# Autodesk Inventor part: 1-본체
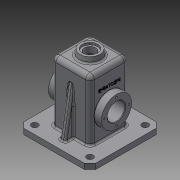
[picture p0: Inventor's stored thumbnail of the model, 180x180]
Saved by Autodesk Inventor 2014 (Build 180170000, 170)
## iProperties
Created: 2016-02
Part Number: 1-본체
Material: 일반
Document SubType Name: Modeling
Designer: HGY
Density: 1 g/cm^3
Appearance: 기본값
Author: HGY
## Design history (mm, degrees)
sketch "스케치1"
  geometry: L1 (-35, 35)-(35, 35); L2 (35, 35)-(35, -35); L3 (35, -35)-(-35, -35); L4 (-35, -35)-(-35, 35); L5 (-35, 35)-(35, -35); L6 (35, 35)-(-35, -35); 1 further point
  constraints: 12 end point, 2 midpoint, 2 parallel, 2 perpendicular, 1 horizontal
  dimensions: "d0" = 70 distance of L1.end L2.end
extrude "돌출1" new body sketch "스케치1" distance "d1" = 120; taper "d2" = 0 deg
sketch "스케치2"
  geometry: L1 (-65, 65)-(65, 65); L2 (65, 65)-(65, -65); L3 (65, -65)-(-65, -65); L4 (-65, -65)-(-65, 65); L5 (-65, 65)-(65, -65); L6 (65, 65)-(-65, -65); 1 further point
  constraints: 12 end point, 2 midpoint, 2 parallel, 2 perpendicular, 1 horizontal
  dimensions: "d3" = 130 distance of L1.end L2.end
extrude "돌출2" join sketch "스케치2" distance "d4" = 10; taper "d5" = 0 deg
fillet "모깎기1" dims "d6" = 8
fillet "모깎기2" dims "d7" = 8
feature "쉘1" dims "d8" = 10, "d9" = 5
sketch "스케치3"
  geometry: L1 (-27, 120)-(27, 120) reference; L2 (35, 112)-(35, 10) reference; L3 (35, 10)-(65, 10) reference; L4 (65, 10)-(65, 0) reference; L5 (65, 0)-(30, 0) reference; L6 (30, 0)-(30, 112) reference; L7 (27, 115)-(-27, 115) reference; L8 (-30, 112)-(-30, 0) reference; L9 (-30, 0)-(-65, 0) reference; L10 (-65, 0)-(-65, 10) reference; L11 (-65, 10)-(-35, 10) reference; L12 (-35, 10)-(-35, 112) reference; L13 (0, 120)-(0, 130); L14 (0, 130)-(-18.237, 130); L15 (-18.237, 130)-(-20, 120); A1 r 8 centre (-27, 112) between (-27, 120) and (-35, 112) reference; A2 r 8 centre (27, 112) between (35, 112) and (27, 120) reference; A3 r 3 centre (27, 112) between (30, 112) and (27, 115) reference; A4 r 3 centre (-27, 112) between (-27, 115) and (-30, 112) reference; 1 further point
  constraints: 6 end point, 1 midpoint, 1 parallel, 1 perpendicular, 1 point on line
  dimensions: "d11" = 10 deg angle of L8 L15; "d13" = 40 diameter of L15.end L13; "d14" = 10 distance between parallel lines of L1 L14
revolve "회전1" sketch "스케치3" stored, may be unused: angle "d15" = 90 deg
sketch "스케치6"
  geometry: C1 r 27.5 at (-45, 27); 1 further point
  constraints: 1 centre point, 1 horizontal alignment
  dimensions: "d26" = 55 diameter of C1; "d27" = 55 distance of C1.centre point (10, 27)
extrude "돌출5" join sketch "스케치6" distance "d28" = 13; taper "d29" = 0 deg
fillet "모깎기5" dims "d30" = 0.5
sketch "스케치8"
  geometry: L1 (35, 112)-(35, 10) reference; L2 (35, 10)-(65, 10) reference; L3 (65, 10)-(65, 0) reference; L4 (65, 0)-(30, 0) reference; L5 (30, 0)-(30, 112) reference; L6 (27, 115)-(-27, 115) reference; L7 (-30, 112)-(-30, 0) reference; L8 (-30, 0)-(-65, 0) reference; L9 (-65, 0)-(-65, 10) reference; L10 (-65, 10)-(-35, 10) reference; L11 (-35, 10)-(-35, 27) reference; L12 (-35.5, 27.5)-(-48, 27.5) reference; L13 (-48, 27.5)-(-48, 82.5) reference; L14 (-48, 82.5)-(-35.5, 82.5) reference; L15 (-35, 83)-(-35, 112) reference; L16 (-27, 120)-(-20, 120) reference; L17 (-20, 120)-(-18.237, 130) reference; L18 (-18.237, 130)-(18.237, 130) reference; L19 (18.237, 130)-(20, 120) reference; L20 (20, 120)-(27, 120) reference; L21 (-30, 55)-(-23, 55); L22 (-23, 55)-(-23, 75.5); L23 (-23, 75.5)-(-30, 82.5); A1 r 8 centre (27, 112) between (35, 112) and (27, 120) reference; A2 r 3 centre (27, 112) between (30, 112) and (27, 115) reference; A3 r 3 centre (-27, 112) between (-27, 115) and (-30, 112) reference; A4 r 0.5 centre (-35.5, 27) between (-35, 27) and (-35.5, 27.5) reference; A5 r 0.5 centre (-35.5, 83) between (-35.5, 82.5) and (-35, 83) reference; A6 r 8 centre (-27, 112) between (-27, 120) and (-35, 112) reference; 3 further points
  constraints: 6 end point, 2 midpoint, 2 point on line, 1 horizontal alignment, 1 parallel, 1 perpendicular
  dimensions: "d31" = 135 deg angle of L7 L23; "d32" = 55 diameter of L23.end L21; "d33" = 7 distance between parallel lines of L7 L22
revolve "회전2" sketch "스케치8" stored, may be unused: angle "d34" = 90 deg
hole "구멍1" diameter "d37" = 32; stored, may be unused: countersink angle "d41" = 90 deg, drill point angle "d43" = 118 deg; dims "d35" = 10, "d36" = 10, "d38" = 6, "d39" = 4, "d40" = 2, "d42" = 8
sketch "스케치9"
  geometry: L1 (0, 0)-(-22.5, 0); C1 r 27.5 at (0, 0) reference; 1 further point
  constraints: 2 end point, 1 horizontal
  dimensions: "d44" = 22.5 distance of L1.start L1.end
hole "구멍2" sketch "스케치9" at (-22.5, 0) diameter "d45" = 3.242; stored, may be unused: countersink angle "d49" = 90 deg, drill point angle "d51" = 118 deg; dims "d46" = 8, "d47" = 4, "d48" = 2, "d50" = 10
fillet "모깎기6" dims "d55" = 0.5
sketch "스케치10"
  geometry: L1 (-18.237, 130)-(18.237, 130) reference; L2 (18.237, 130)-(20, 120) reference; L3 (20, 120)-(27, 120) reference; L4 (35, 112)-(35, 10) reference; L5 (35, 10)-(65, 10) reference; L6 (65, 10)-(65, 0) reference; L7 (65, 0)-(30, 0) reference; L8 (30, 0)-(30, 112) reference; L9 (27, 115)-(-27, 115) reference; L10 (-30, 112)-(-30, 0) reference; L11 (-30, 0)-(-65, 0) reference; L12 (-65, 0)-(-65, 10) reference; L13 (-65, 10)-(-35, 10) reference; L14 (-35, 10)-(-35, 112) reference; L15 (-27, 120)-(-20, 120) reference; L16 (-20, 120)-(-18.237, 130) reference; L17 (-50, 10)-(-35, 95.069); A1 r 8 centre (27, 112) between (35, 112) and (27, 120) reference; A2 r 3 centre (27, 112) between (30, 112) and (27, 115) reference; A3 r 3 centre (-27, 112) between (-27, 115) and (-30, 112) reference; A4 r 8 centre (-27, 112) between (-27, 120) and (-35, 112) reference; 1 further point
  constraints: 2 end point, 1 midpoint, 1 point on line
  dimensions: "d56" = 15 distance of L17.start L12.end; "d57" = 10 deg angle of L12 L17
feature "리브1" sketch "스케치10" dims "d58" = 1, "d59" = 10, "d60" = 0, "d61" = 0, "d62" = 1, "d63" = 1
fillet "모깎기7" dims "d64" = 3
fillet "모깎기8" dims "d65" = 3
chamfer "모따기1" distance "d66" = 1; stored, may be unused: second distance "d67" = 2, angle "d68" = 45 deg
hole "구멍3" diameter "d71" = 21; stored, may be unused: countersink angle "d75" = 90 deg, drill point angle "d77" = 118 deg; dims "d69" = 10, "d70" = 10, "d72" = 8, "d73" = 28, "d74" = 4, "d76" = 10
sketch "스케치11"
  geometry: L1 (-50, -50)-(50, -50); L2 (50, -50)-(50, 50); L3 (50, 50)-(-50, 50); L4 (-50, 50)-(-50, -50); L5 (-50, -50)-(50, 50); L6 (50, -50)-(-50, 50); 1 further point
  constraints: 12 end point, 2 midpoint, 2 parallel, 2 perpendicular, 1 horizontal
  dimensions: "d78" = 100 distance of L2.end L3.end
hole "구멍4" sketch "스케치11" at (-50, -50), (50, 50), (50, -50), (-50, 50) diameter "d79" = 12; stored, may be unused: countersink angle "d83" = 90 deg, drill point angle "d85" = 118 deg; dims "d80" = 8, "d81" = 28, "d82" = 4, "d84" = 10
chamfer "모따기2" distance "d86" = 10; stored, may be unused: second distance "d87" = 2, angle "d88" = 45 deg
fillet "모깎기9" dims "d89" = 3
sketch "스케치12"
  geometry: L1 (-8, 54)-(-8, 0) reference; L2 (99, 62)-(0, 62) reference; 2 further points
  constraints: 1 other
  dimensions: "d90" = 30 distance from line of L1 point (22, 27); "d91" = 35 distance from line of L2 point (22, 27)
feature "엠보싱1" sketch "스케치12" dims "d0" = 70, "d92" = 0.5, "d93" = 0
fillet "모깎기10" dims "d94" = 3
fillet "모깎기11" dims "d95" = 0.5
sketch "스케치13"
  geometry: 1 further point
node "솔리드1"
pattern_circular "원형 패턴1" dims angle "d53" = 360 deg
mirror "대칭1"
mirror "대칭2"
node "절단 모서리 투영1"
node "절단 모서리 투영2"
node "절단 모서리 투영3"
